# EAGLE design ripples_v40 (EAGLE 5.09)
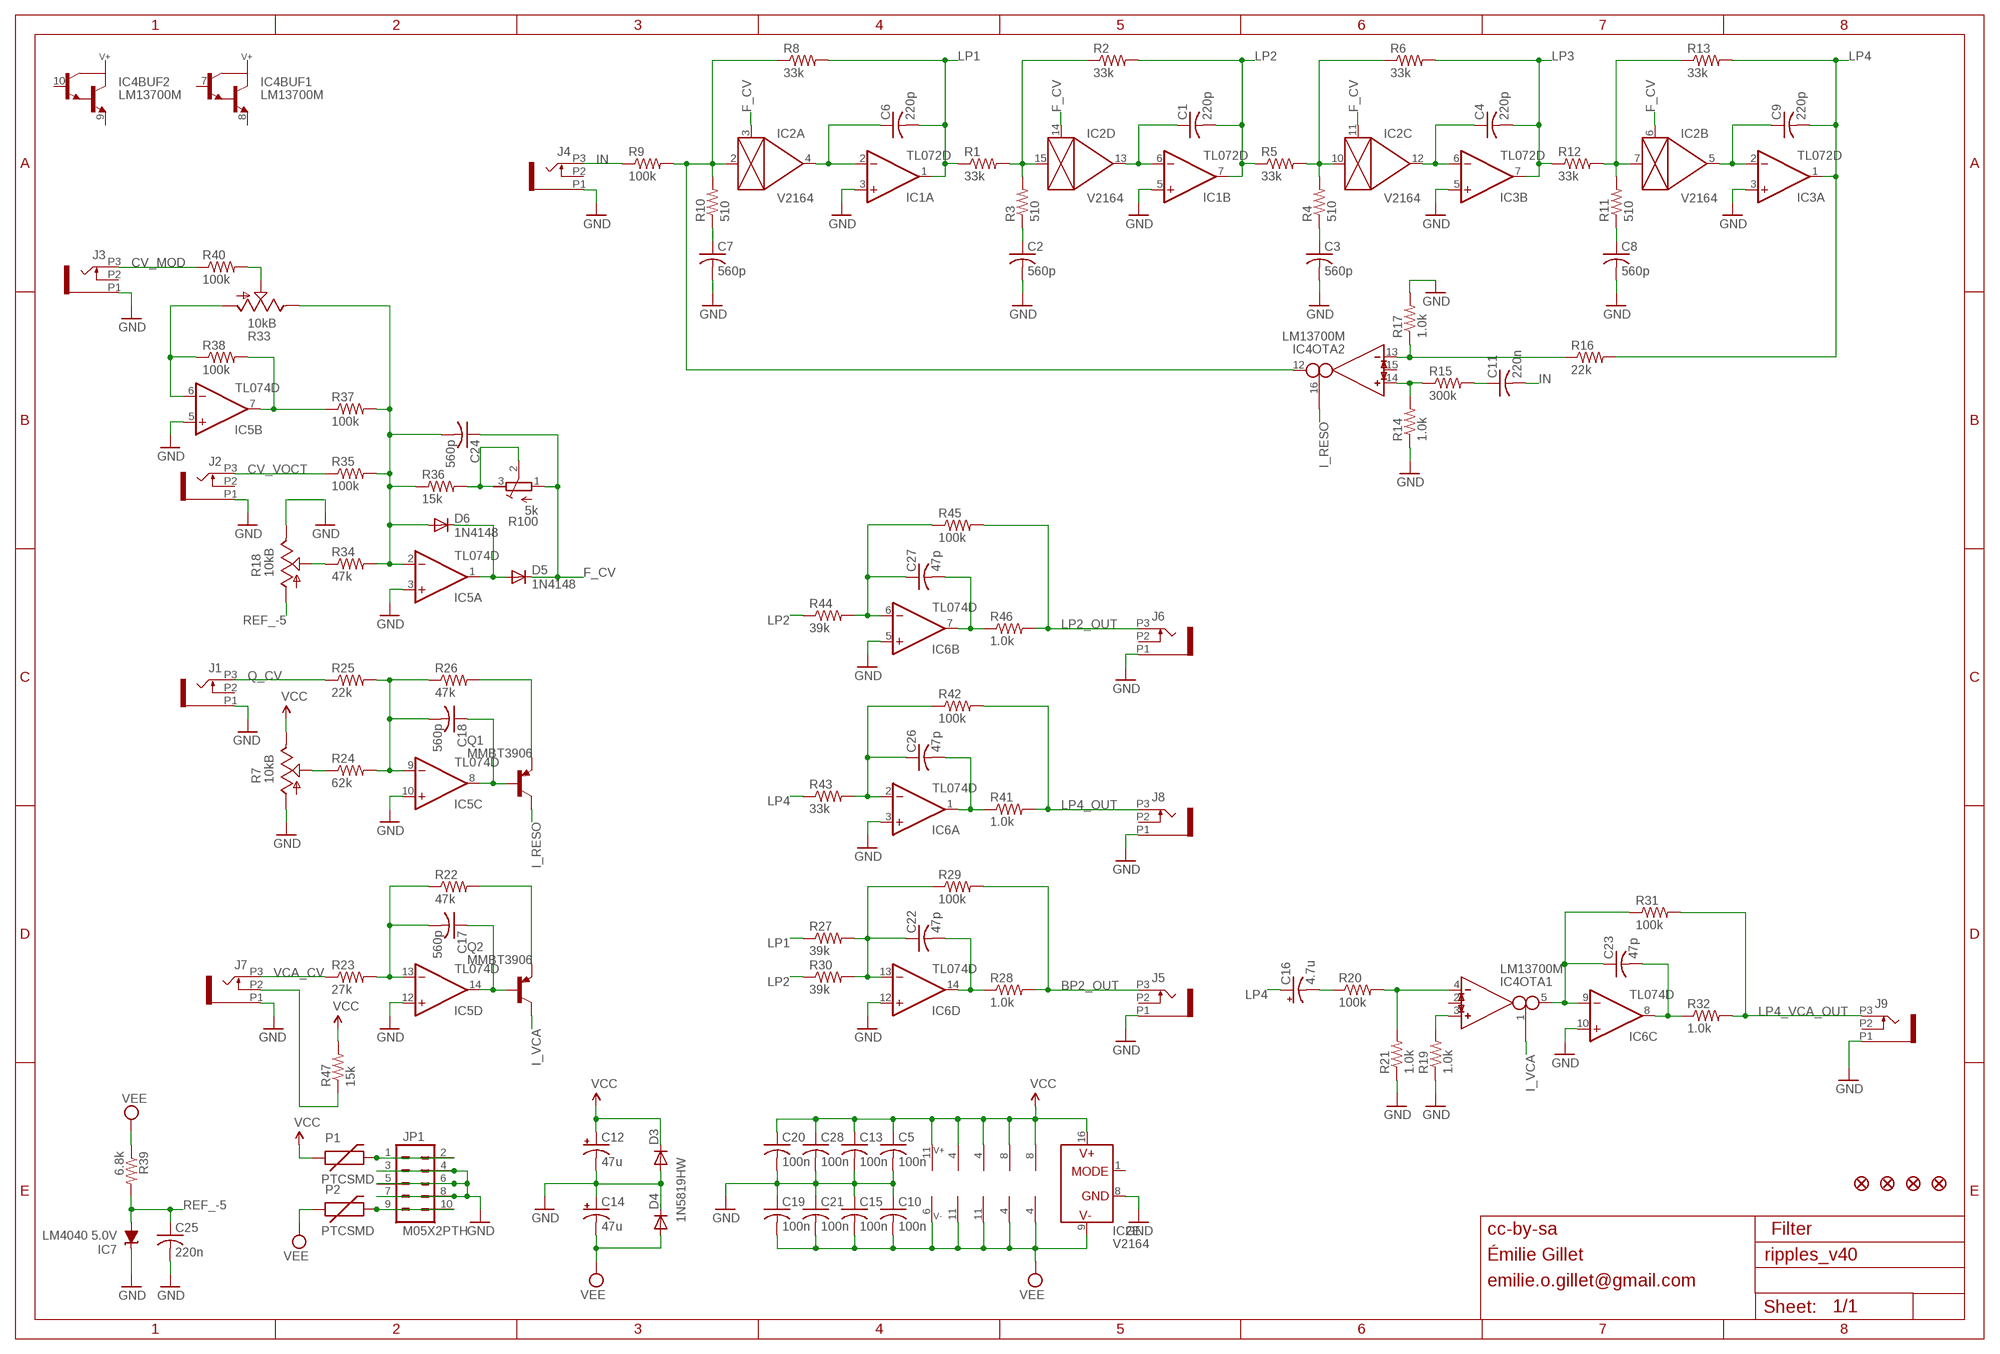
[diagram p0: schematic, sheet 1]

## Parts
C1  220p  C-USC0603  [C0603]
C2  560p  C-USC0603  [C0603]
C3  560p  C-USC0603  [C0603]
C4  220p  C-USC0603  [C0603]
C5  100n  C-USC0603  [C0603]
C6  220p  C-USC0603  [C0603]
C7  560p  C-USC0603  [C0603]
C8  560p  C-USC0603  [C0603]
C9  220p  C-USC0603  [C0603]
C10  100n  C-USC0603  [C0603]
C11  220n  C-USC0603  [C0603]
C12  47u  CPOL-USD  [PANASONIC_D]
C13  100n  C-USC0603  [C0603]
C14  47u  CPOL-USD  [PANASONIC_D]
C15  100n  C-USC0603  [C0603]
C16  4.7u  CPOL-USB  [PANASONIC_B]
C17  560p  C-USC0603  [C0603]
C18  560p  C-USC0603  [C0603]
C19  100n  C-USC0603  [C0603]
C20  100n  C-USC0603  [C0603]
C21  100n  C-USC0603  [C0603]
C22  47p  C-USC0603  [C0603]
C23  47p  C-USC0603  [C0603]
C24  560p  C-USC0603  [C0603]
C25  220n  C-USC0603  [C0603]
C26  47p  C-USC0603  [C0603]
C27  47p  C-USC0603  [C0603]
C28  100n  C-USC0603  [C0603]
D3  1N5819HW  DIODE-SOD123  [SOD123]
D4  1N5819HW  DIODE-SOD123  [SOD123]
D5  1N4148  DIODE-SOD323-W  [SOD323-W]
D6  1N4148  DIODE-SOD323-W  [SOD323-W]
F1  FIDUCIAL1X2  [FIDUCIAL-1X2]
F2  FIDUCIAL1X2  [FIDUCIAL-1X2]
F3  FIDUCIAL1X2  [FIDUCIAL-1X2]
F4  FIDUCIAL1X2  [FIDUCIAL-1X2]
IC1  TL072D  [SO08]
IC2  V2164  SSM2164S  [SOIC16N]
IC3  TL072D  [SO08]
IC4  LM13700M  [SO16]
IC5  TL074D  [SO14]
IC6  TL074D  [SO14]
IC7  LM4040 5.0V  LM4041C12DBZ  [DBZ_R-PDSO-G3]
J1  PJ301_THONKICONN6  [WQP_PJ_301M6]
J2  PJ301_THONKICONN6  [WQP_PJ_301M6]
J3  PJ301_THONKICONN6  [WQP_PJ_301M6]
J4  PJ301_THONKICONN6  [WQP_PJ_301M6]
J5  PJ301_THONKICONN6  [WQP_PJ_301M6]
J6  PJ301_THONKICONN6  [WQP_PJ_301M6]
J7  PJ301_THONKICONN6  [WQP_PJ_301M6]
J8  PJ301_THONKICONN6  [WQP_PJ_301M6]
J9  PJ301_THONKICONN6  [WQP_PJ_301M6]
JP1  M05X2PTH  [AVR_ICSP]
P1  PTCSMD  [PTC-1206]
P2  PTCSMD  [PTC-1206]
Q1  MMBT3906  MMBT3906LT1-PNP-SOT23-BEC  [SOT23-BEC]
Q2  MMBT3906  MMBT3906LT1-PNP-SOT23-BEC  [SOT23-BEC]
R1  33k  R-US_R0603  [R0603]
R2  33k  R-US_R0603  [R0603]
R3  510  R-US_R0603  [R0603]
R4  510  R-US_R0603  [R0603]
R5  33k  R-US_R0603  [R0603]
R6  33k  R-US_R0603  [R0603]
R7  10kB  POT_USVERTICAL_PS  [ALPS_POT_VERTICAL_PS]
R8  33k  R-US_R0603  [R0603]
R9  100k  R-US_R0603  [R0603]
R10  510  R-US_R0603  [R0603]
R11  510  R-US_R0603  [R0603]
R12  33k  R-US_R0603  [R0603]
R13  33k  R-US_R0603  [R0603]
R14  1.0k  R-US_R0603  [R0603]
R15  300k  R-US_R0603  [R0603]
R16  22k  R-US_R0603  [R0603]
R17  1.0k  R-US_R0603  [R0603]
R18  10kB  POT_USVERTICAL_PS  [ALPS_POT_VERTICAL_PS]
R19  1.0k  R-US_R0603  [R0603]
R20  100k  R-US_R0603  [R0603]
R21  1.0k  R-US_R0603  [R0603]
R22  47k  R-US_R0603  [R0603]
R23  27k  R-US_R0603  [R0603]
R24  62k  R-US_R0603  [R0603]
R25  22k  R-US_R0603  [R0603]
R26  47k  R-US_R0603  [R0603]
R27  39k  R-US_R0603  [R0603]
R28  1.0k  R-US_R0603  [R0603]
R29  100k  R-US_R0603  [R0603]
R30  39k  R-US_R0603  [R0603]
R31  100k  R-US_R0603  [R0603]
R32  1.0k  R-US_R0603  [R0603]
R33  10kB  POT_USVERTICAL_PS  [ALPS_POT_VERTICAL_PS]
R34  47k  R-US_R0603  [R0603]
R35  100k  R-US_R0603  [R0603]
R36  15k  R-US_R0603  [R0603]
R37  100k  R-US_R0603  [R0603]
R38  100k  R-US_R0603  [R0603]
R39  6.8k  R-US_R0603  [R0603]
R40  100k  R-US_R0603  [R0603]
R41  1.0k  R-US_R0603  [R0603]
R42  100k  R-US_R0603  [R0603]
R43  33k  R-US_R0603  [R0603]
R44  39k  R-US_R0603  [R0603]
R45  100k  R-US_R0603  [R0603]
R46  1.0k  R-US_R0603  [R0603]
R47  15k  R-US_R0603  [R0603]
R100  5k  R-TRIMM3296X  [RTRIM3296X]

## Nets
BP2_OUT: J5.P3 R28.2 R29.2
CV_F_POT: R18.P$2(S) R34.1
CV_MOD: J3.P3 R40.1
CV_VOCT: J2.P3 R35.1
F_CV: C24.1 D5.C IC2.3(A:CTRL) IC2.6(B:CTRL) IC2.11(C:CTRL) IC2.14(D:CTRL) R100.1(E)
GND: C2.2 C3.2 C5.2 C7.2 C8.2 C10.1 C12.- C13.2 C14.+ C15.1 C19.1 C20.2 C21.1 C25.2 C28.2 D3.A D4.C IC1.3(A:+IN) IC1.5(B:+IN) IC2.8(E:GND) IC3.3(A:+IN) IC3.5(B:+IN) IC5.3(A:+IN) IC5.5(B:+IN) IC5.10(C:+IN) IC5.12(D:+IN) IC6.3(A:+IN) IC6.5(B:+IN) IC6.10(C:+IN) IC6.12(D:+IN) IC7.1(C) J1.P1 J2.P1 J3.P1 J4.P1 J5.P1 J6.P1 J7.P1 J8.P1 J9.P1 JP1.3 JP1.4 JP1.5 JP1.6 JP1.7 JP1.8 R7.P$3(A) R14.1 R17.2 R18.P$1(E) R19.1 R21.1
I_RESO: IC4.16(OTA2:I_BIAS) Q1.C
I_VCA: IC4.1(OTA1:I_BIAS) Q2.C
IN: C11.2 J4.P3 R9.1
LP1: C6.2 IC1.1(A:OUT) R1.1 R8.2 R27.1
LP2: C1.2 IC1.7(B:OUT) R2.2 R5.1 R30.1 R44.1
LP2_OUT: J6.P3 R45.2 R46.2
LP3: C4.2 IC3.7(B:OUT) R6.2 R12.1
LP4: C9.2 C16.+ IC3.1(A:OUT) R13.2 R16.2 R43.1
LP4_OUT: J8.P3 R41.2 R42.2
LP4_VCA_OUT: J9.P3 R31.2 R32.2
N$1: IC5.7(B:OUT) R37.1 R38.2
N$2: C6.1 IC1.2(A:-IN) IC2.4(A:OUT)
N$3: IC2.15(D:IN) R1.2 R2.1 R3.2
N$4: R36.2 R100.2(S) R100.3(A)
N$5: IC4.3(OTA1:IN_P) R19.2
N$6: JP1.1 JP1.2 P1.2
N$7: C11.1 R15.2
N$8: C7.1 R10.1
N$9: C1.1 IC1.6(B:-IN) IC2.13(D:OUT)
N$10: IC2.2(A:IN) IC4.12(OTA2:OUT) R8.1 R9.2 R10.2
N$11: C2.1 R3.1
N$12: IC2.10(C:IN) R4.2 R5.2 R6.1
N$13: C4.1 IC2.12(C:OUT) IC3.6(B:-IN)
N$14: IC4.13(OTA2:IN_N) R16.1 R17.1
N$15: C3.1 R4.1
N$16: IC2.7(B:IN) R11.2 R12.2 R13.1
N$17: C9.1 IC2.5(B:OUT) IC3.2(A:-IN)
N$18: IC4.14(OTA2:IN_P) R14.2 R15.1
N$19: C8.1 R11.1
N$20: JP1.9 JP1.10 P2.2
N$21: R33.P$2(S) R40.2
N$22: IC5.6(B:-IN) R33.P$3(A) R38.1
N$23: C24.2 D6.A IC5.2(A:-IN) R33.P$1(E) R34.2 R35.2 R36.1 R37.2
N$24: R7.P$2(S) R24.1
N$25: C17.2 IC5.13(D:-IN) R22.1 R23.2
N$26: C18.2 IC5.9(C:-IN) R24.2 R25.2 R26.1
N$27: C18.1 IC5.8(C:OUT) Q1.B
N$28: Q1.E R26.2
N$29: J7.P2 R47.1
N$30: C17.1 IC5.14(D:OUT) Q2.B
N$31: Q2.E R22.2
N$32: C27.1 IC6.6(B:-IN) R44.2 R45.1
N$33: C26.1 IC6.2(A:-IN) R42.1 R43.2
N$37: C26.2 IC6.1(A:OUT) R41.1
N$38: D5.A D6.C IC5.1(A:OUT)
N$39: C27.2 IC6.7(B:OUT) R46.1
N$40: C22.1 IC6.13(D:-IN) R27.2 R29.1 R30.2
N$41: C22.2 IC6.14(D:OUT) R28.1
N$42: IC4.4(OTA1:IN_N) R20.2 R21.2
N$43: C23.1 IC4.5(OTA1:OUT) IC6.9(C:-IN) R31.1
N$44: C23.2 IC6.8(C:OUT) R32.1
N$68: C16.- R20.1
Q_CV: J1.P3 R25.1
REF_-5: C25.1 IC7.2(A) R18.P$3(A) R39.2
VCA_CV: J7.P3 R23.1
VCC: C5.1 C12.+ C13.1 C20.1 C28.1 D3.C IC1.8(P:V+) IC2.16(E:V+) IC3.8(P:V+) IC4.11(SUPPLY:V+) IC5.4(P:V+) IC6.4(P:V+) P1.1 R7.P$1(E) R47.2
VEE: C10.2 C14.- C15.2 C19.2 C21.2 D4.A IC1.4(P:V-) IC2.9(E:V-) IC3.4(P:V-) IC4.6(SUPPLY:V-) IC5.11(P:V-) IC6.11(P:V-) P2.1 R39.1
Unconnected: IC2.1(E:MODE) IC4.2(OTA1:I_DIODE) IC4.7(BUF1:B) IC4.8(BUF1:E) IC4.9(BUF2:E) IC4.10(BUF2:B) IC4.15(OTA2:I_DIODE) J1.P2 J2.P2 J3.P2 J4.P2 J5.P2 J6.P2 J8.P2 J9.P2

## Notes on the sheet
- cc-by-sa | Filter
- Émilie Gillet
- emilie.o.gillet@gmail.com

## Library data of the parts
C1-C11 C13 C15 C17-C28 = rcl:C-US: CAPACITOR, American symbol
C12 C14 C16 = rcl:CPOL-US: POLARIZED CAPACITOR, American symbol
D3-D6 = diode:DIODE-: DIODE
F1-F4 = SparkFun:FIDUCIAL: Fiducial Alignment Points
IC1 IC3 = og-linear:TL072: OP AMP
IC2 = ssm2164:SSM2164
IC4 = ota:LM13700: Dual OTA with buffers
IC5 IC6 = gm-ics:TL074: OP AMP
IC7 = texas:LM4041: PRECISION MICROPOWER SHUNT VOLTAGE REFERENCE
J1-J9 = og-pj301:PJ301_THONKICONN
JP1 = og-header:M05X2: Header 5x2 Standard 10-pin dual row 0.1" header. Commonly used with AVR-ISP. Use with Spark Fun Electronics SKU: PRT-00778
P1 P2 = SparkFun:PTC: Resettable Fuse PTC
Q1 Q2 = transistor:*-PNP-: PNP Transistror
R1-R6 R8-R17 R19-R32 R34-R38 R40-R47 = rcl:R-US_: RESISTOR, American symbol
R7 R18 R33 = pot-alps:POT_US
R39 = resistor:R-US_: RESISTOR, American symbol
R100 = rcl:R-TRIMM: Trimm resistor

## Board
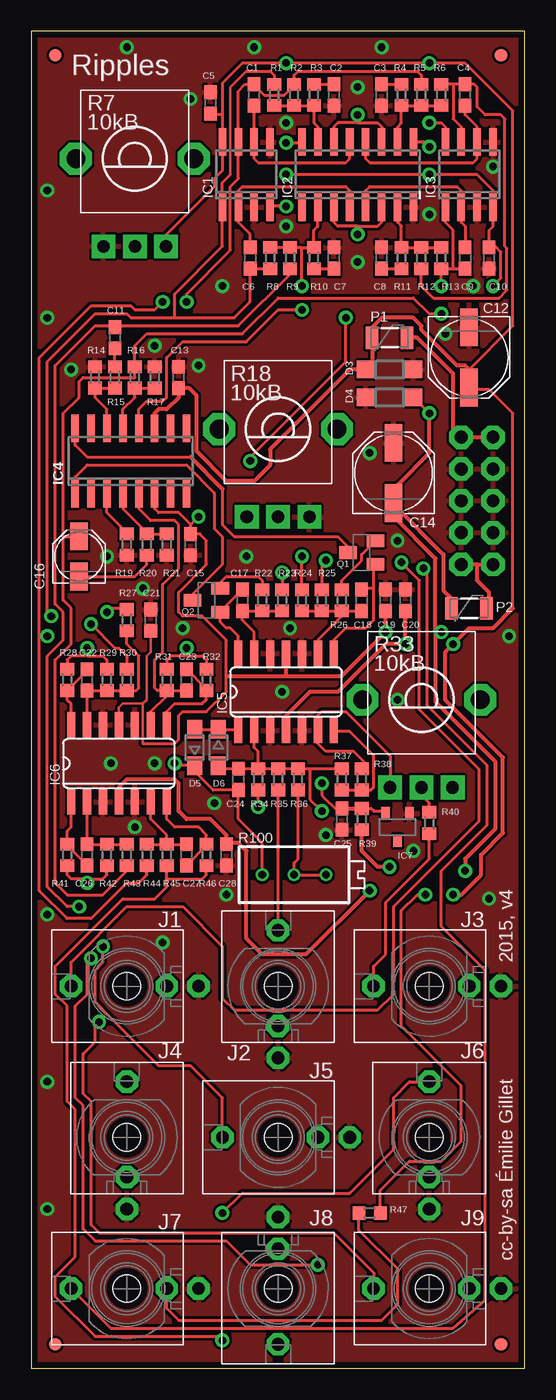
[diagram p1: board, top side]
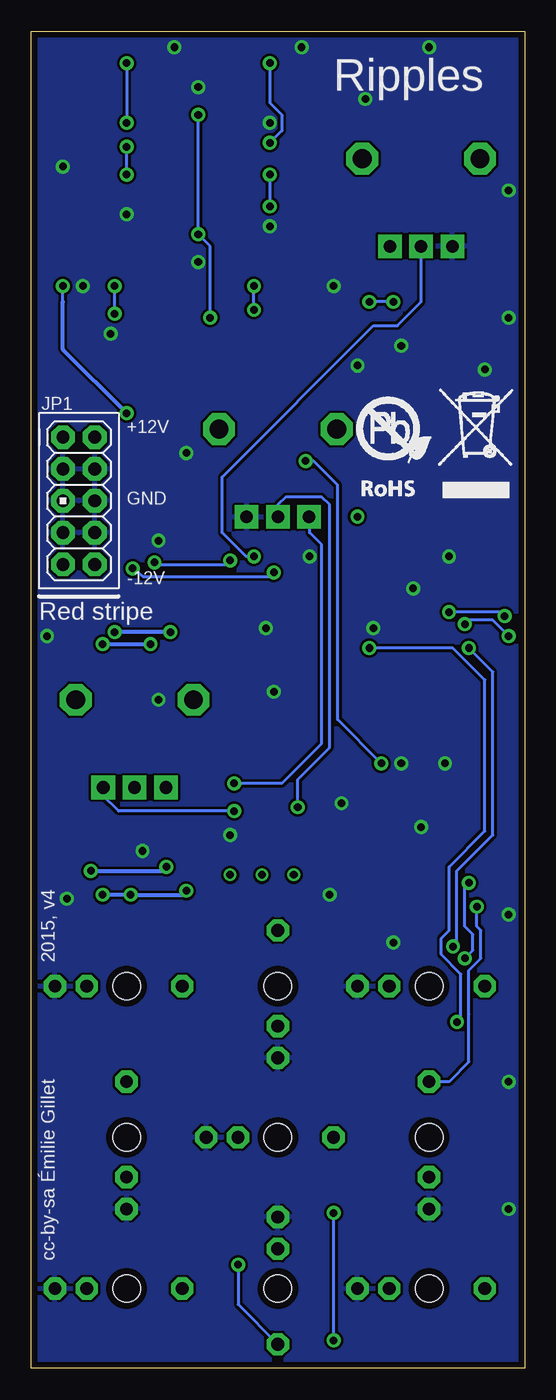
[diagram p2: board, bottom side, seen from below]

Size 39.35 x 106.68 mm. Coordinates in mm from the lower left corner, seen from the top.
Outline: 0,0 39.35,0 39.35,106.68 0,106.68 0,0
Copper layers (1*16): Top 0.035mm / dielectric 1.5mm / Bottom 0.035mm
Design rules "PCBCart-Standard *": minimum track width 8mil, minimum drill 0.4mm, track to track 8mil, track to pad 8mil, pad to pad 8mil, via to via 8mil, smd to smd 8mil, copper to edge 20mil, drill to drill 8mil, minimum pad ring 8mil, minimum via ring 10mil, stop-mask expansion 3mil, vias tented up to drill 25mil, thermal gap 8mil

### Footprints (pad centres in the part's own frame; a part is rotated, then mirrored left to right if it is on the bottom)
C0603 = smd 1.1 x 1: 1 -0.85,0; 2 0.85,0
PANASONIC_D = smd 3 x 1.4: + 2.4,0; - -2.4,0
PANASONIC_B = smd 2.2 x 1.4: + 1.6,0; - -1.6,0
SOD123 = smd 1.4 x 1.4: A 1.9,0; C -1.9,0
SOD323-W = smd 1.5 x 1.2: A 1.45,0; C -1.45,0
FIDUCIAL-1X2 = smd 1 x 1: 1 0,0
SO08 = smd 0.6 x 2.2: 1 -1.905,-2.6; 2 -0.635,-2.6; 3 0.635,-2.6; 4 1.905,-2.6; 5 1.905,2.6; 6 0.635,2.6; 7 -0.635,2.6; 8 -1.905,2.6
SOIC16N = smd 0.6 x 2.2: 1 -4.445,-2.6; 2 -3.175,-2.6; 3 -1.905,-2.6; 4 -0.635,-2.6; 5 0.635,-2.6; 6 1.905,-2.6; 7 3.175,-2.6; 8 4.445,-2.6; 9 4.445,2.6; 10 3.175,2.6; 11 1.905,2.6; 12 0.635,2.6; 13 -0.635,2.6; 14 -1.905,2.6; 15 -3.175,2.6; 16 -4.445,2.6
SO16 = smd 0.6 x 2.2: 1 -4.445,-2.6; 2 -3.175,-2.6; 3 -1.905,-2.6; 4 -0.635,-2.6; 5 0.635,-2.6; 6 1.905,-2.6; 7 3.175,-2.6; 8 4.445,-2.6; 9 4.445,2.6; 10 3.175,2.6; 11 1.905,2.6; 12 0.635,2.6; 13 -0.635,2.6; 14 -1.905,2.6; 15 -3.175,2.6; 16 -4.445,2.6
SO14 = smd 0.66 x 2.032: 1 -3.81,-3.073; 2 -2.54,-3.073; 3 -1.27,-3.073; 4 0,-3.073; 5 1.27,-3.073; 6 2.54,-3.073; 7 3.81,-3.073; 8 3.81,3.073; 9 2.54,3.073; 10 1.27,3.073; 11 0,3.073; 12 -1.27,3.073; 13 -2.54,3.073; 14 -3.81,3.073
DBZ_R-PDSO-G3 = smd 0.7 x 1: 1 -0.95,-1.1; 2 0.95,-1.1; 3 0,1.1
WQP_PJ_301M6 = drill 1.016 pad 1.778 octagon: P1 0,-5.715; P2 0,-3.175; P3 0,4.445 | hole 2.2: 0,0
AVR_ICSP = drill 1.016 pad 1.88 octagon: 1 -1.27,5.08; 2 1.27,5.08; 3 -1.27,2.54; 4 1.27,2.54; 5 -1.27,0; 6 1.27,0; 7 -1.27,-2.54; 8 1.27,-2.54; 9 -1.27,-5.08; 10 1.27,-5.08
PTC-1206 = smd 1 x 1.8: 1 -1.4,0; 2 1.4,0
SOT23-BEC = smd 1 x 1.4: B -0.95,-1.1; C 0,1.1; E 0.95,-1.1
R0603 = smd 1 x 1.1: 1 -0.85,0; 2 0.85,0
ALPS_POT_VERTICAL_PS = drill 1 pad 1.88 square: P$1 -2.5,7; P$2 0,7; P$3 2.5,7 | drill 1.5 pad 2.54 octagon: P$4 -4.7,0; P$5 4.7,0
RTRIM3296X = drill 0.61 round: 1 0,-2.54; 2 0,0; 3 0,2.54

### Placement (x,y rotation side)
C1  17.78,101.6 90 top
C2  24.13,101.6 270 top
C3  27.94,101.6 270 top
C4  34.61,101.6 90 top
C5  14.29,100.97 90 top
C6  17.46,88.58 270 top
C7  24.13,88.58 90 top
C8  27.94,88.58 90 top
C9  34.61,88.58 270 top
C10  36.51,88.58 90 top
C11  6.67,82.23 90 top
C12  34.92,80.64 270 top
C13  11.75,79.06 90 top
C14  28.89,71.44 90 top
C15  12.7,65.72 90 top
C16  3.81,64.77 90 top
C17  16.83,61.28 270 top
C18  26.35,61.28 270 top
C19  28.26,61.28 270 top
C20  29.84,61.28 90 top
C21  9.53,59.69 270 top
C22  4.45,54.93 90 top
C23  12.38,54.93 90 top
C24  16.51,46.99 90 top
C25  24.77,43.81 270 top
C26  4.45,40.96 270 top
C27  12.38,40.96 270 top
C28  15.56,40.96 270 top
D3  28.57,79.69 0 top
D4  28.57,77.47 0 top
D5  13.02,49.53 90 top
D6  14.92,49.53 270 top
F1  1.91,104.78 90 top
F2  37.47,104.78 90 top
F3  1.91,1.91 90 top
F4  37.47,1.91 90 top
IC1  17.14,95.25 0 top
IC2  26.04,95.25 0 top
IC3  34.92,95.25 0 top
IC4  7.94,72.39 0 top
IC5  20.32,53.98 0 top
IC6  6.99,48.26 0 top
IC7  29.21,43.18 180 top
J1  7.62,30.48 90 top
J2  19.68,30.48 0 top
J3  31.75,30.48 90 top
J4  7.62,18.41 0 top
J5  19.68,18.41 90 top
J6  31.75,18.41 0 top
J7  7.62,6.35 90 top
J8  19.68,6.35 180 top
J9  31.75,6.35 90 top
JP1  35.56,69.22 0 bottom
P1  28.57,82.23 0 top
P2  34.92,60.64 0 top
Q1  26.35,65.09 90 top
Q2  13.97,61.28 90 top
R1  19.37,101.6 270 top
R2  20.95,101.6 90 top
R3  22.54,101.6 270 top
R4  29.53,101.6 270 top
R5  31.11,101.6 270 top
R6  32.7,101.6 90 top
R7  8.26,96.52 180 top
R8  19.05,88.58 270 top
R9  20.64,88.58 90 top
R10  22.54,88.58 90 top
R11  29.53,88.58 90 top
R12  31.11,88.58 90 top
R13  32.7,88.58 270 top
R14  5.08,79.06 270 top
R15  6.67,79.06 90 top
R16  8.26,79.06 90 top
R17  9.84,79.06 90 top
R18  19.68,74.93 180 top
R19  7.62,65.72 90 top
R20  9.21,65.72 90 top
R21  10.79,65.72 90 top
R22  18.41,61.28 90 top
R23  20,61.28 270 top
R24  21.59,61.28 270 top
R25  23.18,61.28 270 top
R26  24.77,61.28 90 top
R27  7.62,59.69 270 top
R28  2.86,54.93 90 top
R29  6.03,54.93 90 top
R30  7.62,54.93 270 top
R31  10.79,54.93 90 top
R32  13.97,54.93 90 top
R33  31.11,53.34 180 top
R34  18.1,46.99 90 top
R35  19.68,46.99 90 top
R36  21.27,46.99 270 top
R37  24.77,46.99 90 top
R38  26.35,46.99 270 top
R39  26.35,43.81 90 top
R40  31.75,43.5 90 top
R41  2.86,40.96 270 top
R42  6.03,40.96 270 top
R43  7.62,40.96 90 top
R44  9.21,40.96 90 top
R45  10.79,40.96 270 top
R46  13.97,40.96 270 top
R47  26.99,12.38 0 top
R100  20.95,39.37 270 top
U$2  [ROHS]  14.29,68.9 0 bottom

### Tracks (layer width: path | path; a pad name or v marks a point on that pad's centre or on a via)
BP2_OUT  (via drill 0.6)
  Top 0.254: R28.2 2.86,56.52 3.17,56.83 4.45,56.83 | R29.2 6.03,56.52 5.71,56.83 4.45,56.83 | v4.45,57.47 4.45,56.83 | v5.71,33.66 5.71,32.38 5.08,31.75 5.08,29.21 6.35,27.94 7.62,26.67 10.16,24.13 12.7,24.13 15.24,21.59 J5.P3
  Bottom 0.254: v4.45,57.47 2.54,55.56 2.54,42.55 5.4,39.69 5.4,33.97 v5.71,33.66
CV_F_POT  (via drill 0.6)
  Top 0.254: v18.1,44.77 R34.1
  Bottom 0.254: v18.1,44.77 18.1,46.99 15.56,49.53 15.56,68.9 16.19,69.53 19.05,69.53 19.68,68.9 R18.P$2
CV_MOD
  Top 0.254: R40.1 31.75,40.64 28.26,37.15 28.26,33.02 27.3,32.07 J3.P3
CV_VOCT
  Top 0.254: J2.P3 R35.1
F_CV  (via drill 0.6)
  Top 0.254: IC2.11 27.94,99.06 27.62,99.38 26.04,99.38 | 26.04,99.38 24.45,99.38 24.13,99.06 IC2.14 | IC2.3 24.13,91.44 24.45,91.12 26.04,91.12 | IC2.6 27.94,91.44 27.62,91.12 26.04,91.12 | v26.04,90.49 26.04,91.12 | v26.04,100.01 26.04,99.38 | v17.46,72.39 17.46,72.71 25.08,80.33 v25.08,83.82 | v11.43,48.26 11.61,48.08 D5.C 13.02,47.62 14.5,46.14 C24.1 16.51,43.81 18.41,41.91 R100.1
  Bottom 0.254: v26.04,100.01 v26.04,90.49 25.08,89.53 v25.08,83.82 | v11.43,48.26 14.92,51.75 14.92,70.48 16.83,72.39 v17.46,72.39
GND  (via drill 0.6)
  other vias: 26.04,102.23 26.04,88.27 20.32,99.38 20.32,91.12 31.75,92.08 36.83,95.89 35.24,86.36 12.7,101.28 9.84,81.6 3.17,79.69 8.89,62.23 6.03,64.77 12.06,59.05 13.34,80.01 6.35,48.26 8.26,43.18 33.02,82.55 26.99,73.03 29.21,66.04 30.48,41.27 14.61,45.09 23.5,42.55 20.64,59.05 17.14,64.77 9.84,48.26 20,53.98 1.27,36.2 10.48,33.97 7.62,105.41 17.78,105.41 27.94,105.41 1.27,93.98 1.27,83.82 38.1,58.42 36.51,37.47 1.27,22.86 1.27,12.7 29.21,53.34 15.24,86.36 15.56,37.78
  pour Bottom: 0,106.68 0,0 39.37,0 39.37,106.68
  pour Top: 0,106.68 0,0 39.37,0 39.37,106.68
I_RESO
  Top 0.254: IC4.16 3.49,73.66 4.45,72.71 12.7,72.71 | 15.24,70.17 15.24,67.31 16.19,66.36 24.45,66.36 25.25,65.55 Q1.C
  Top 0.305: 12.7,72.71 15.24,70.17
I_VCA
  Top 0.254: IC4.1 3.49,71.12 4.45,72.07 12.38,72.07 14.61,69.85 14.61,66.99 15.24,66.36 15.24,64.14 12.87,61.77 Q2.C
IN  (via drill 0.6)
  Top 0.254: R9.1 20.64,87.31 16.51,83.19 6.67,83.19 | 6.67,83.19 5.08,83.19 1.91,80.01 1.91,60.96 2.54,60.33 2.54,58.1 1.27,56.83 1.27,38.42 2.86,36.83 v3.81,36.83 | 6.67,83.19 C11.2
  Bottom 0.254: J4.P3 6.03,22.86 4.45,24.45 4.45,28.26 4.45,31.75 3.49,32.7 3.49,34.92 3.81,35.24 v3.81,36.83
LP1  (via drill 0.6)
  Top 0.203: 15.88,95.25 15.88,102.23
  Top 0.254: R8.2 C6.2 17.46,85.09 16.19,83.82 11.43,83.82 | 15.88,95.25 15.24,94.61 IC1.1 15.24,89.53 11.43,85.72 11.43,83.82 | 15.88,102.23 17.14,103.5 19.05,103.5 19.37,103.19 R1.1 | 11.43,83.82 7.94,83.82 7.62,84.14 5.08,84.14 1.27,80.33 1.27,60.33 v1.59,60.01 | R27.1 7.52,60.64 6.35,60.64 v6.03,60.33
  Bottom 0.254: v1.59,60.01 1.91,60.33 v6.03,60.33
LP2  (via drill 0.6)
  Top 0.254: R5.1 31.11,103.19 30.8,103.5 21.27,103.5 20.95,103.19 R2.2 20.95,102.39 20.16,101.6 18.57,101.6 17.78,102.39 C1.2 17.04,102.45 16.51,101.92 IC1.7 16.51,94.93 15.88,94.3 15.88,89.22 12.38,85.72 v12.38,85.09 | v10.48,85.09 9.84,84.45 8.26,84.45 7.94,84.77 4.76,84.77 0.64,80.64 0.64,58.42 | 0.64,58.42 0.64,38.1 2.86,35.88 4.76,35.88 7.62,38.73 8.57,38.73 9.21,39.37 R44.1 | R30.1 7.62,56.83 6.99,57.47 6.67,57.47 v4.76,59.37 | 0.64,58.42 v1.27,58.42
  Bottom 0.254: v10.48,85.09 v12.38,85.09 | v1.27,58.42 2.54,59.69 4.45,59.69 v4.76,59.37
LP2_OUT  (via drill 0.6)
  Top 0.254: R46.2 13.97,39.37 13.65,39.05 10.79,39.05 | 10.79,39.05 10.79,38.42 9.84,37.47 7.3,37.47 1.91,32.07 1.91,29.84 2.86,28.89 2.86,21.27 3.49,20.64 3.49,8.89 1.91,7.3 1.91,5.71 5.08,2.54 14.92,2.54 v15.24,2.22 | 10.79,39.05 R45.2 | v15.24,12.38 16.83,13.97 25.4,13.97 28.89,17.46 28.89,21.59 30.16,22.86 J6.P3
  Bottom 0.254: v15.24,2.22 v15.24,12.38
LP3
  Top 0.254: 33.66,102.45 R6.2 | 33.66,102.45 C4.2 35.34,102.45 35.56,102.23 35.56,100.65 36.2,100.01 37.47,100.01 37.78,99.69 37.78,89.53 37.94,89.38 37.94,86.04 37.31,85.41 32.07,85.41 31.11,86.36 R12.1 | IC3.7 34.29,99.06 33.66,99.69 33.66,102.45
LP4  (via drill 0.6)
  Top 0.254: 33.66,87.73 R13.2 v32.7,86.36 | 33.66,87.73 C9.2 | IC3.1 33.02,91.44 33.66,90.81 33.66,87.73 | v32.7,84.14 31.75,84.14 30.48,85.41 19.68,85.41 16.83,82.55 9.21,82.55 8.26,81.6 R16.2 8.26,79.06 4.13,79.06 3.81,78.74 3.81,77.47 2.54,76.2 2.54,66.36 | R43.1 7.62,39.69 5.71,37.78 2.86,37.78 1.91,38.73 1.91,56.52 3.17,57.78 3.17,60.64 2.54,61.28 2.54,66.36 | C16.+ 3.67,66.67 3.35,66.36 2.54,66.36
  Bottom 0.254: v32.7,84.14 v32.7,86.36
LP4_OUT  (via drill 0.6)
  Top 0.254: R42.2 6.03,39.37 5.71,39.05 4.45,39.05 | R41.2 2.86,39.37 3.17,39.05 4.45,39.05 | v4.45,38.73 4.45,39.05 | v4.76,32.7 4.45,32.38 4.45,29.84 3.49,28.89 3.49,21.59 4.13,20.95 4.13,11.11 5.08,10.16 15.56,10.16 17.46,8.26 v22.86,8.26
  Bottom 0.254: v4.45,38.73 4.76,38.42 4.76,35.24 4.13,34.61 4.13,33.34 v4.76,32.7 | v22.86,8.26 22.86,5.08 J8.P3
LP4_VCA_OUT  (via drill 0.6)
  Top 0.254: R32.2 13.97,56.52 13.65,56.83 12.38,56.83 | R31.2 10.79,56.52 11.11,56.83 12.38,56.83 | v12.38,57.47 12.38,56.83 | v5.4,27.62 5.08,27.3 5.08,26.04 4.13,25.08 4.13,21.91 4.76,21.27 4.76,11.43 5.4,10.79 24.13,10.79 27.3,7.62 J9.P3
  Bottom 0.254: v12.38,57.47 5.71,57.47 3.17,54.93 3.17,42.86 6.03,40.01 6.03,34.92 6.67,34.29 6.67,33.02 5.08,31.43 5.08,27.94 v5.4,27.62
N$1
  Top 0.254: IC5.7 24.23,50.8 25.4,50.8 27.3,48.9 27.3,46.35 27.09,46.14 R38.2 R37.1
N$2
  Top 0.254: IC2.4 25.4,93.98 25.08,94.3 16.83,94.3 16.51,93.98 IC1.2 16.51,91.44 17.46,90.49 C6.1 17.43,89.4
N$3
  Top 0.254: IC2.15 22.86,99.06 22.54,99.38 R3.2 R2.1 R1.2
N$4
  Top 0.254: R36.2 21.27,40.64 20.95,40.32 R100.2 R100.3
N$5
  Top 0.254: IC4.3 6.03,68.26 7.62,66.67 R19.2
N$6
  Top 0.305: P1.2 29.66,82.23 30.8,82.23 33.66,79.38 33.66,74.93 JP1.2 JP1.1
N$7
  Top 0.254: R15.2 C11.1
N$8
  Top 0.254: R10.1 C7.1
N$9
  Top 0.254: IC2.13 25.4,96.52 25.08,96.2 18.1,96.2 17.78,96.52 IC1.6 C1.1
N$10  (via drill 0.6)
  Top 0.254: R8.1 R9.2 21.59,89.43 | 21.59,89.43 R10.2 22.54,90.81 22.86,91.12 IC2.2 | IC4.12 8.57,76.52 9.21,77.15 10.48,77.15 10.79,77.47 10.79,80.64 12.06,81.92 17.14,81.92 19.68,84.45 v21.59,84.45 | v21.59,86.36 21.59,89.43
  Bottom 0.254: v21.59,84.45 v21.59,86.36
N$11
  Top 0.254: R3.1 C2.1
N$12
  Top 0.254: IC2.10 29.21,99.06 29.53,99.38 R4.2 R5.2 R6.1
N$13
  Top 0.254: IC2.12 26.67,96.52 26.99,96.2 35.24,96.2 35.56,96.52 IC3.6 35.56,99.06 34.61,100.01 C4.1
N$14
  Top 0.254: IC4.13 7.3,76.52 8.26,77.47 R16.1 R17.1
N$15
  Top 0.254: C3.1 R4.1
N$16
  Top 0.254: IC2.7 29.21,91.44 29.53,91.12 R11.2 R12.2 R13.1
N$17
  Top 0.254: IC2.5 26.67,93.98 26.99,94.3 33.97,94.3 34.29,93.98 IC3.2 34.29,91.44 34.61,91.12 C9.1
N$18
  Top 0.254: IC4.14 6.03,76.52 5.08,77.47 R14.2 R15.1
N$19
  Top 0.254: C8.1 R11.1
N$20
  Top 0.305: 35.56,64.14 JP1.10 | 35.56,64.14 JP1.9 | P2.2 36.51,61.47 36.51,61.91 35.56,62.87 35.56,64.14
N$21
  Top 0.254: R40.2 31.75,45.09 31.11,45.72 R33.P$2
N$22
  Top 0.254: R38.1 26.67,48.26 25.72,49.21 23.5,49.21 22.86,49.85 IC5.6 22.86,52.07 23.18,52.39 25.08,52.39 28.61,48.85 R33.P$3
N$23  (via drill 0.6)
  Top 0.254: D6.A 15.48,47.84 C24.2 R34.2 | IC5.2 17.78,49.53 18.1,49.21 R34.2 | 22.23,47.84 R36.1 R35.2 R34.2 | v23.18,44.45 22.23,45.4 22.23,47.84 | 22.23,47.84 R37.2
  Bottom 0.254: R33.P$1 33.66,46.3 33.66,45.72 32.38,44.45 v23.18,44.45
N$24  (via drill 0.6)
  Top 0.254: R24.1 v21.59,64.77
  Bottom 0.254: v21.59,64.77 22.23,64.77 24.13,66.67 24.13,71.12 12.06,83.19 10.16,83.19 8.26,85.09 R7.P$2
N$25
  Top 0.254: R23.2 R22.1 C17.2 16.83,59.69 17.78,58.74 IC5.13
N$26
  Top 0.254: R26.1 C18.2 | R24.2 R25.2 R26.1 | IC5.9 22.86,58.1 24.77,60.01 R26.1
N$27
  Top 0.254: IC5.8 24.13,58.1 25.08,59.05 26.67,59.05 27.3,59.69 27.3,62.23 | 27.3,62.23 27.3,63.67 27.45,63.82 Q1.B | C18.1 26.45,62.23 27.3,62.23
N$28
  Top 0.254: Q1.E 26.35,64.94 26.35,64.45 24.77,62.87 R26.2
N$29
  Top 0.254: R47.1 26.14,11.01 29.21,7.94 29.21,5.08 27.94,3.81 11.75,3.81 10.79,4.76 J7.P2
N$30
  Top 0.254: IC5.14 16.51,58.42 15.88,59.05 15.56,59.05 15.07,59.54 Q2.B 15.07,60.37 C17.1
N$31
  Top 0.254: R22.2 18.41,62.87 18.1,63.18 15.56,63.18 15.07,62.7 Q2.E
N$32
  Top 0.254: R44.2 R45.1 | R45.1 C27.1 | IC6.6 9.53,43.81 10.79,42.55 R45.1
N$33
  Top 0.254: R43.2 R42.1 C26.1 IC6.2
N$37
  Top 0.254: C26.2 2.86,41.7 R41.1 2.86,42.86 3.17,43.18 IC6.1
N$38
  Top 0.254: IC5.1 16.43,50.98 D6.C D5.A
N$39
  Top 0.254: IC6.7 10.79,43.81 11.43,43.18 13.34,43.18 13.97,42.55 R46.1 13.97,41.7 C27.2
N$40
  Top 0.254: IC6.13 C22.1 R29.1 R30.2 8.36,54.08 8.57,54.29 8.57,56.83 7.62,57.78 R27.2 7.72,58.74
N$41
  Top 0.254: IC6.14 3.17,53.02 2.86,53.34 R28.1 4.45,55.66 C22.2
N$42
  Top 0.254: R21.2 R20.2 9.21,66.67 7.3,68.58 IC4.4
N$43
  Top 0.254: R31.1 C23.1 | R31.1 10.06,54.08 9.84,54.29 9.84,56.52 10.48,57.15 10.48,62.55 11.75,63.82 11.75,67.31 11.43,67.63 9.53,67.63 8.57,68.58 IC4.5 | IC6.9 9.53,52.39 10.79,53.66 R31.1
N$44
  Top 0.254: C23.2 13.97,54.19 R32.1 13.97,53.34 13.65,53.02 11.43,53.02 10.79,52.39 IC6.8
N$68
  Top 0.254: R20.1 9.21,64.14 8.24,63.17 C16.-
Q_CV  (via drill 0.6)
  Top 0.254: v29.53,64.29 30.96,62.87 30.96,52.55 35.72,47.78 35.72,43.66 28.89,36.83 28.89,29.84 27.62,28.57 16.19,28.57 15.24,29.53 15.24,33.66 12.06,36.83 7.62,36.83 3.17,32.38 J1.P3 | v23.5,64.45 23.18,64.14 R25.1
  Bottom 0.254: v23.5,64.45 23.81,64.14 29.37,64.14 v29.53,64.29
REF_-5  (via drill 0.6)
  Top 0.254: C25.1 24.98,44.45 24.45,44.45 23.18,45.72 v23.18,46.67 | IC7.2 28.09,44.45 27.3,44.45 27.09,44.66 R39.2
  Top 0.305: C25.1 R39.2
  Bottom 0.254: R18.P$3 17.14,67.89 17.14,66.67 16.19,65.72 16.19,49.85 19.37,46.67 v23.18,46.67
VCA_CV  (via drill 0.6)
  Top 0.254: v20,63.5 R23.1 | v31.27,63.82 31.59,63.5 31.59,52.86 36.35,48.1 36.35,43.34 32.7,39.69 32.7,35.24 36.2,31.75 36.2,5.4 33.66,3.17 6.35,3.17 J7.P3
  Bottom 0.254: v31.27,63.82 30.48,63.18 20.32,63.18 v20,63.5
VCC  (via drill 0.6)
  Top 0.254: C13.1 11.85,78.11 | R7.P$1 10.76,90.45 14.61,94.3 14.61,94.93 15.24,95.57 IC1.8 15.24,100.01 | IC3.8 33.02,99.06 32.7,99.38 v31.75,99.38 | 15.24,100.01 15.24,102.55 16.83,104.14 v20.32,104.14 v31.75,104.14 34.61,104.14 38.42,100.33 38.42,83.19 34.92,79.69 | 15.24,100.01 14.39,100.01 | v20.32,97.79 21.53,97.79 | 35.06,78.11 36.51,78.11 38.42,76.2 38.42,60.64 | v31.43,37.78 30.8,37.78 29.53,36.51 29.53,27.3 34.29,22.54 34.29,18.1 32.7,16.51 30.16,16.51 27.84,14.19 R47.2
  Top 0.305: IC4.11 9.84,76.2 10.16,76.52 10.79,76.52 11.75,77.47 C13.1 12.6,78.21 13.18,77.63 13.18,73.18 15.56,70.8 17.78,70.8 19.05,72.07 19.05,73.34 25.4,79.69 D3.C | IC6.4 6.99,46.35 7.62,46.99 11.43,46.99 11.75,46.67 11.75,44.45 12.38,43.81 14.29,43.81 15.56,42.55 C28.1 15.66,41.91 16.51,41.91 17.14,41.27 17.14,34.29 18.41,33.02 21.91,33.02 v26.99,38.1 | IC5.4 20.32,52.07 22.23,53.98 24.45,53.98 28.26,57.78 v29.84,57.78 C20.1 29.84,59.69 | v33.66,37.78 34.29,37.78 35.88,39.37 35.88,40.96 37.62,42.7 37.62,48.74 33.02,53.34 33.02,57.15 v33.66,57.78 34.92,59.05 36.83,59.05 38.42,60.64 | P1.1 26.99,82.05 | D3.C | D3.C 27.18,80.19 P1.1 | P1.1 27.18,83.06 27.94,83.82 30.48,83.82 31.11,83.19 31.11,82.87 33.97,80.01 34.61,80.01 34.92,79.69 C12.+ 35.06,78.11 | 14.39,100.01 C5.1 | 21.53,97.79 IC2.16
  Bottom 0.254: v31.75,104.14 v31.75,99.38 | v20.32,97.79 19.37,98.74 19.37,100.01 20.32,100.97 v20.32,104.14
  Bottom 0.305: v33.66,57.78 v29.84,57.78 | v33.66,37.78 v31.43,37.78 27.3,37.78 v26.99,38.1
VEE  (via drill 0.6)
  Top 0.203: C21.2 9.53,57.15 9.21,56.83 9.21,53.34 8.89,53.02 | IC6.11 6.99,52.7 7.3,53.02 8.89,53.02 | 8.89,53.02 8.89,49.85
  Top 0.254: IC1.4 19.11,92.71 v20.32,92.71 | v20.32,95.25 v31.75,95.25 35.56,95.25 36.83,93.98 IC3.4 36.83,91.12 36.51,90.81 C10.2 36.62,89.53 36.99,89.53 37.47,89.06 37.47,87 v36.83,86.36 | v31.75,97.47 31.37,97.85 IC2.9 | C14.- 29.21,69.36 | 8.89,49.85 11.43,49.85 11.75,50.16 11.75,52.07 12.06,52.39 13.97,52.39 15.56,53.98 15.56,55.24 15.56,58.1 13.65,60.01 12.06,60.01 11.75,60.33 11.75,61.91 13.97,64.14 13.97,66.04 13.44,66.57 C15.2 12.7,67.31 | IC4.6 9.84,68.58 10.16,68.26 11.75,68.26 12.7,67.31 | 12.7,67.31 v13.34,67.94 | D4.A v31.75,76.2
  Top 0.305: 29.21,69.36 29.21,70.48 31.75,73.03 v31.75,76.2 | 29.39,69.04 C14.- 28.89,68.9 | 32.23,58.74 32.23,64.61 28.89,67.94 28.89,68.9 | C19.2 v28.26,58.74 24.77,55.24 20.32,55.24 | R39.1 26.35,41.27 27.62,40.01 v28.57,40.01 | v34.61,39.69 34.61,40.64 36.99,43.02 36.99,48.42 32.23,53.18 32.23,58.74 | v32.7,58.74 32.23,58.74 | 15.56,55.24 20.32,55.24 | 20.32,55.24 IC5.11 | 28.89,68.9 32.86,64.93 32.86,62.07 33.52,61.41 P2.1
  Bottom 0.254: 36.83,85.09 v36.83,86.36 | v31.75,95.25 v31.75,97.47 | v20.32,95.25 v20.32,92.71
  Bottom 0.305: 36.83,85.09 36.83,81.28 v31.75,76.2 | v28.26,58.74 v32.7,58.74 | v34.61,39.69 28.89,39.69 v28.57,40.01

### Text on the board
bPlace: Red stripe
tNames: Ripples | 2015, v4 | cc-by-sa Émilie Gillet
bNames: Ripples | +12V | GND | -12V | 2015, v4 | cc-by-sa Émilie Gillet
